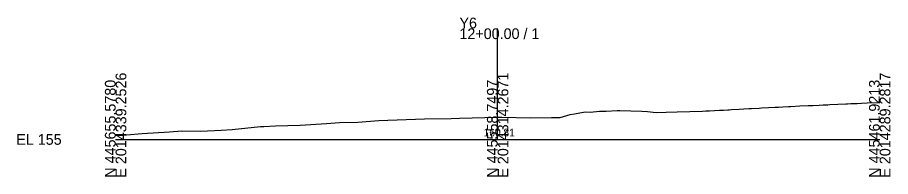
# Model space of a CAD drawing. Extents: x -26 to 203, y -10 to 4529.
# Drawn here: x -25.7 to 202.8, y 3990.3 to 4031.9 of the extents above; entities that cross this region are included whole.
import ezdxf

# ---------------------------------------------------------------- set-up
doc = ezdxf.new("R2010")
doc.units = 0
for name, color, linetype in [('Default', 7, 'Continuous'), ('Exist Cross Section Cell', 7, 'Continuous'), ('Exist XS Center Line Elevation Label', 7, 'Continuous'), ('Exist XS Ground Line', 7, 'Continuous')]:
    doc.layers.add(name, color=color, linetype=linetype)

msp = doc.modelspace()

# ---------------------------------------------------------------- linework, layer by layer
at = {"layer": 'Exist Cross Section Cell'}
for p, q in [((100, 4000), (100, 4029.06)), ((0, 4000), (100, 4000)), ((100, 4000), (200, 4000))]:
    msp.add_line(p, q, dxfattribs=at)
at = {"layer": 'Exist XS Ground Line'}
msp.add_lwpolyline([(0, 4001.01), (1.85, 4001.16), (5.92, 4001.43), (6.97, 4001.54), (14.13, 4002.02), (17.3, 4002.23), (22.34, 4002.21), (27.63, 4002.42), (30.55, 4002.64), (37.96, 4003.36), (38.76, 4003.41), (41.88, 4003.53), (48.28, 4003.75), (55.18, 4004.18), (58.61, 4004.45), (63.39, 4004.51), (68.94, 4004.94), (80.87, 4005.36), (87.81, 4005.47), (90.05, 4005.53), (100, 4005.81), (101.06, 4005.84), (108.67, 4005.64), (114.06, 4005.7), (116.35, 4005.75), (119, 4006.55), (120.1, 4006.68), (122.9, 4007.2), (124.23, 4007.15), (126.68, 4007.42), (128.44, 4007.36), (131.24, 4007.54), (132.01, 4007.59), (137.77, 4007.36), (139.23, 4007.33), (141.52, 4007.05), (144.1, 4007.11), (147.03, 4007.21), (153.63, 4007.4), (154.47, 4007.45), (154.87, 4007.49), (155.42, 4007.52), (156.74, 4007.59), (158.03, 4007.65), (159.08, 4007.7), (160.21, 4007.76), (160.61, 4007.78), (161.18, 4007.81), (163.18, 4007.92), (164.4, 4007.99), (165.79, 4008.06), (166.43, 4008.09), (168.41, 4008.21), (169.06, 4008.25), (170.92, 4008.34), (172.62, 4008.42), (173.52, 4008.47), (174.63, 4008.53), (176.12, 4008.6), (176.74, 4008.63), (179.08, 4008.75), (181.25, 4008.85), (182.51, 4008.91), (184.18, 4008.98), (185.17, 4009.02), (186.41, 4009.09), (186.98, 4009.11), (189.06, 4009.19), (191.1, 4009.3), (191.61, 4009.32), (192.45, 4009.36), (194.14, 4009.43), (195.21, 4009.47), (196.75, 4009.55), (199.39, 4009.66), (200, 4009.69)], dxfattribs=at)

# ---------------------------------------------------------------- texts
at = {"layer": 'Default'}
msp.add_text('-', height=0.0001, dxfattribs=at).set_placement((0, 4000))
at = {"layer": 'Exist Cross Section Cell'}
for s, p in [('Y6', (90, 4029.06)), ('12+00.00 / 1', (90, 4026.26)), ('EL 155', (-26, 3998.6))]:
    msp.add_text(s, height=2.8, dxfattribs=at).set_placement(p)
for s, p in [('N 445655.5780', (0, 3990)), ('E 2014339.2526', (2.8, 3990)), ('N 445558.7497', (100, 3990)), ('E 2014314.2671', (102.8, 3990)), ('N 445461.9213', (200, 3990)), ('E 2014289.2817', (202.8, 3990))]:
    msp.add_text(s, height=2.8, rotation=90, dxfattribs=at).set_placement(p)
at = {"layer": 'Exist XS Center Line Elevation Label'}
msp.add_text('160.81', height=2, dxfattribs=at).set_placement((96.32, 4000.81))

doc.saveas('drawing.dxf')
